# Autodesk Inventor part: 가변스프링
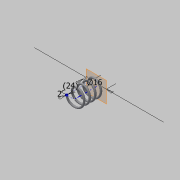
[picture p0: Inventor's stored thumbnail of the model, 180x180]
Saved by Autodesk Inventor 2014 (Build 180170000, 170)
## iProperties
Created: 2015-04
Part Number: 가변스프링
Material: Generic
Document SubType Name: Modeling
Designer: Administrator
Density: 1 g/cm^3
Appearance: Default
Author: Administrator
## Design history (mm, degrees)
sketch "스케치1"
  geometry: L1 (0, 0)-(-8, 0); L2 (-8, 0)-(-8, 16); L3 (-8, 16)-(0, 16); L4 (0, 16)-(0, 0); C1 r 1 at (-8, 0)
  constraints: 8 end point, 2 parallel, 1 centre point, 1 coincident, 1 horizontal, 1 perpendicular
  dimensions: "d0" = 16 diameter of L2 L4; "d1" = 16 distance between parallel lines of L3 L1 (derived); "d2" = 2 diameter of C1
feature "코일1" pitch "d3" = 10; turns "d5" = 4; dims "d4" = 16 (= d1), "d6" = 0, angle "d7" = 90 deg, angle "d8" = 90 deg, "d9" = 0, "d10" = 0
sketch "스케치2"
  geometry: L1 (7, 0)-(9, 0) reference; 1 further point
  constraints: 1 horizontal alignment
extrude "돌출1" cut sketch "스케치2" stored distance "d11" = 10; taper "d12" = 0 deg
node "작업 평면1"
sketch "스케치3"
  geometry: L1 (-7, 0)-(-9, 0) reference; 1 further point
  constraints: 1 horizontal alignment
extrude "돌출2" cut sketch "스케치3" stored distance "d13" = 10; taper "d14" = 0 deg
node "솔리드1"
node "절단 모서리 투영1"
node "절단 모서리 투영2"
